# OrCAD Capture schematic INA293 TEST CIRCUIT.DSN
size B; title: INA293 40-V High-Voltage, High Bandwidth, Unidirectional, 110-V Common-Mode Current-Sense Amplifier; rev: E1; note: SBOS870
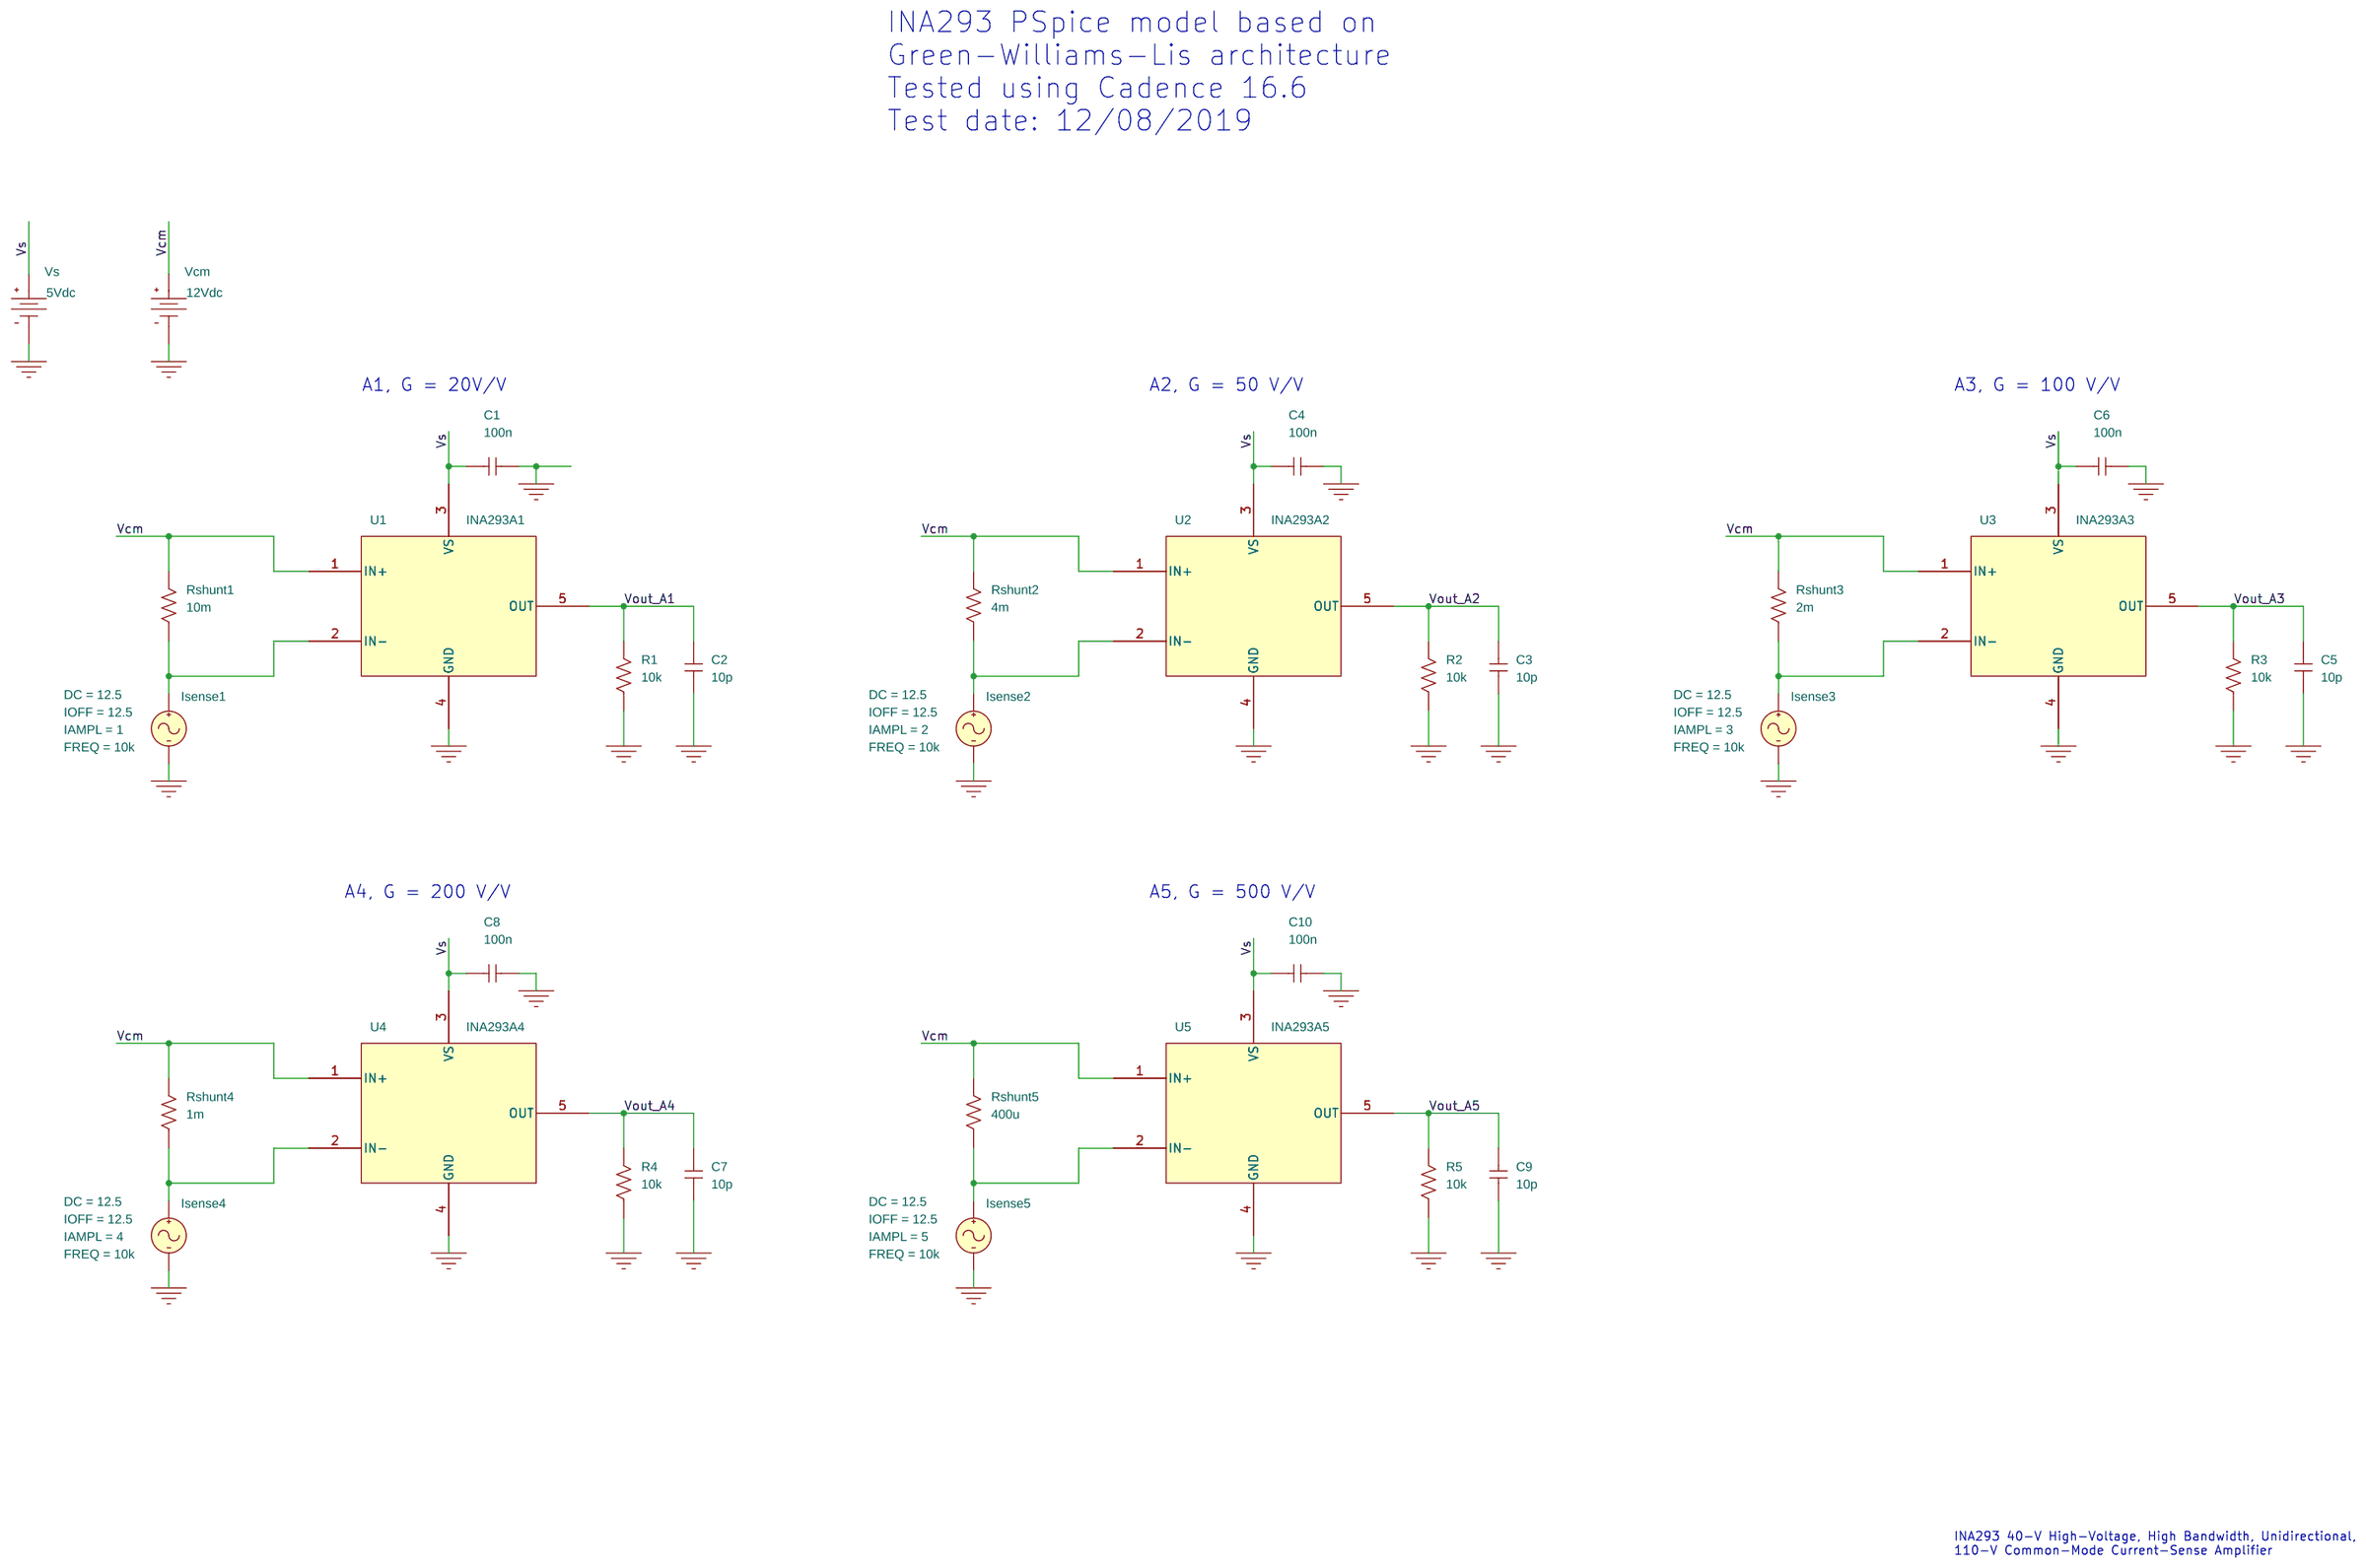
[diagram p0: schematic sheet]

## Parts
C1  100n  [RAD/CK05]
C2  10p  [RAD/CK05]
C3  10p  [RAD/CK05]
C4  100n  [RAD/CK05]
C5  10p  [RAD/CK05]
C6  100n  [RAD/CK05]
C7  10p  [RAD/CK05]
C8  100n  [RAD/CK05]
C9  10p  [RAD/CK05]
C10  100n  [RAD/CK05]
Isense1  ISIN
Isense2  ISIN
Isense3  ISIN
Isense4  ISIN
Isense5  ISIN
R1  10k  [AX/RC05]
R2  10k  [AX/RC05]
R3  10k  [AX/RC05]
R4  10k  [AX/RC05]
R5  10k  [AX/RC05]
Rshunt1  10m  [AX/RC05]
Rshunt2  4m  [AX/RC05]
Rshunt3  2m  [AX/RC05]
Rshunt4  1m  [AX/RC05]
Rshunt5  400u  [AX/RC05]
U1  INA293A1
U2  INA293A2
U3  INA293A3
U4  INA293A4
U5  INA293A5
Vcm  VDC
Vs  VDC

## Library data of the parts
C1-C10 = C
Isense1 = ISIN: DC: 12.5; FREQ: 10k; IAMPL: 1; IOFF: 12.5
Isense2 = ISIN: DC: 12.5; FREQ: 10k; IAMPL: 2; IOFF: 12.5
Isense3 = ISIN: DC: 12.5; FREQ: 10k; IAMPL: 3; IOFF: 12.5
Isense4 = ISIN: DC: 12.5; FREQ: 10k; IAMPL: 4; IOFF: 12.5
Isense5 = ISIN: DC: 12.5; FREQ: 10k; IAMPL: 5; IOFF: 12.5
R1-R5 Rshunt1-Rshunt5 = R
U1 = INA293A1_0
U2 = INA293A2
U3 = INA293A3
U4 = INA293A4
U5 = INA293A5
Vcm = VDC: DC: 12Vdc
Vs = VDC: DC: 5Vdc

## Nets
0: C1.1 C2.1 C3.1 C4.1 C5.1 C6.1 C7.1 C8.1 C9.1 C10.1 Isense1.2(-) Isense2.2(-) Isense3.2(-) Isense4.2(-) Isense5.2(-) R1.1 R2.1 R3.1 R4.1 R5.1 U1.4(GND) U2.4(GND) U3.4(GND) U4.4(GND) U5.4(GND) Vcm.1(-) Vs.1(-)
Vcm: Rshunt1.2 Rshunt2.2 Rshunt3.2 Rshunt4.2 Rshunt5.2 U1.1(IN+) U2.1(IN+) U3.1(IN+) U4.1(IN+) U5.1(IN+) Vcm.0(+)
Vout_A1: C2.2 R1.2 U1.5(OUT)
Vout_A2: C3.2 R2.2 U2.5(OUT)
Vout_A3: C5.2 R3.2 U3.5(OUT)
Vout_A4: C7.2 R4.2 U4.5(OUT)
Vout_A5: C9.2 R5.2 U5.5(OUT)
Vs: C1.2 C4.2 C6.2 C8.2 C10.2 U1.3(VS) U2.3(VS) U3.3(VS) U4.3(VS) U5.3(VS) Vs.0(+)
N06508: Isense1.1(+) Rshunt1.1 U1.2(IN-)
N07297: Isense2.1(+) Rshunt2.1 U2.2(IN-)
N07920: Isense3.1(+) Rshunt3.1 U3.2(IN-)
N08569: Isense4.1(+) Rshunt4.1 U4.2(IN-)
N09240: Isense5.1(+) Rshunt5.1 U5.2(IN-)

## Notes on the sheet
- INA293 PSpice model based on
  Green-Williams-Lis architecture
  Tested using Cadence 16.6
  Test date: 12/08/2019
- A1, G = 20V/V
- A2, G = 50 V/V
- A3, G = 100 V/V
- A4, G = 200 V/V
- A5, G = 500 V/V
- INA293 40-V High-Voltage, High Bandwidth, Unidirectional,
  110-V Common-Mode Current-Sense Amplifier
